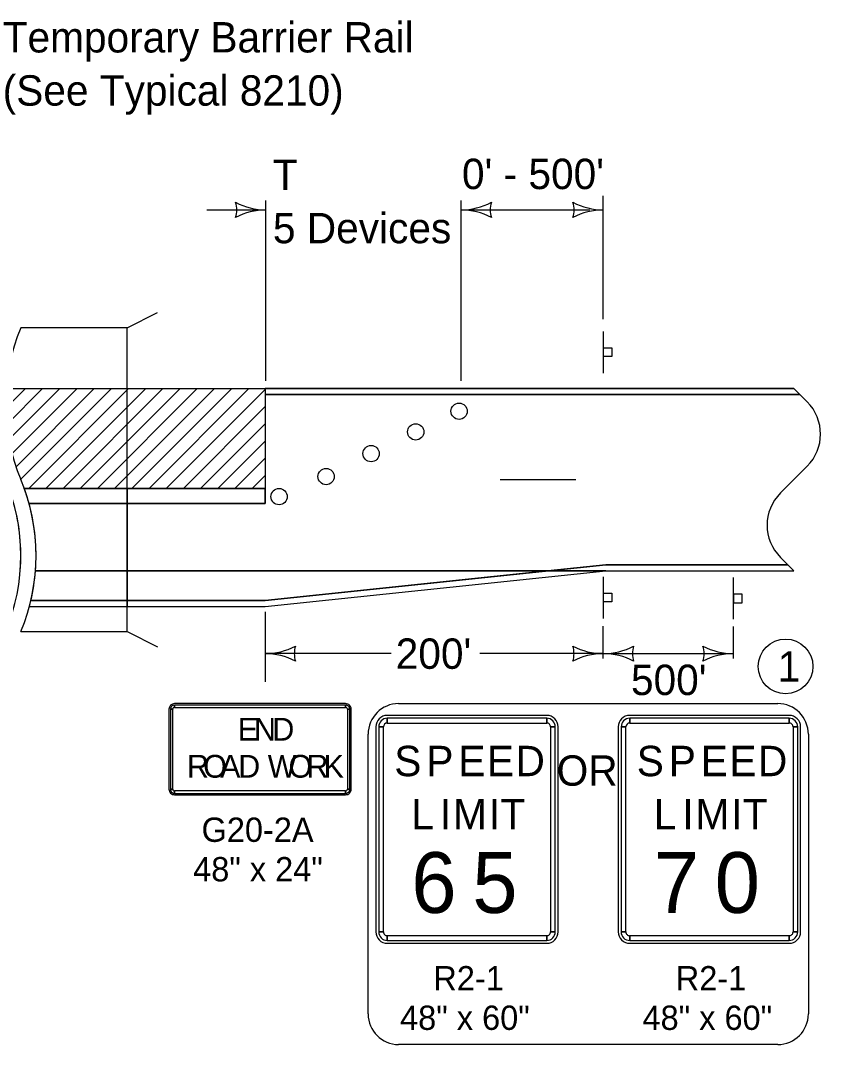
# Model space of a CAD drawing. Extents: x 10133 to 2270741, y 5363 to 1733450.
# Drawn here: x 27091 to 27618, y 6360 to 7034 of the extents above; entities that cross this region are included whole.
import ezdxf

# ---------------------------------------------------------------- set-up
doc = ezdxf.new("R2010")
doc.units = 0
for name, color, linetype in [('dsnNonPlotable', 7, 'Continuous'), ('dsnShtPlotShapeBatchPrint', 7, 'Continuous'), ('dsnStdBorder', 7, 'Continuous'), ('Level 12', 7, 'Continuous'), ('Level 2', 7, 'Continuous')]:
    doc.layers.add(name, color=color, linetype=linetype)

msp = doc.modelspace()

# ---------------------------------------------------------------- linework, layer by layer
at = {"layer": 'dsnNonPlotable'}
for p, q in [((27161.27, 6831.83), (27181.27, 6841.83)), ((27608.87, 6783.04), (27600.09, 6791.83)), ((27591.3, 6723.04), (27608.87, 6740.61)), ((27093.5, 6726.09), (27252.03, 6726.09)), ((27252.03, 6726.09), (27252.03, 6716.09)), ((27252.03, 6716.09), (27096.67, 6716.09)), ((27600.09, 6671.83), (27591.3, 6680.61)), ((27252.03, 6652.32), (27476.23, 6675.83)), ((27100.89, 6671.83), (27476.25, 6671.83)), ((27097.88, 6652.32), (27252.03, 6652.32)), ((27091.27, 6631.83), (27161.27, 6631.83)), ((27161.27, 6631.83), (27181.27, 6621.83))]:
    msp.add_line(p, q, dxfattribs=at)
for points in [[(27161.27, 6631.83), (27161.27, 6831.83), (27091.27, 6831.83)], [(27252.03, 6787.83), (27604.09, 6787.83)], [(27406.7, 6731.83), (27456.7, 6731.83)], [(27406.7, 6731.83), (27456.7, 6731.83)], [(27093.5, 6726.09), (27106.57, 6726.09)], [(27109.74, 6716.09), (27096.67, 6716.09)], [(27476.23, 6675.83), (27596.09, 6675.83)]]:
    msp.add_lwpolyline(points, dxfattribs=at)
for centre, radius, start, end in [((27211.27, 6781.83), 130, 157.38014, 202.61987), ((27587.66, 6761.83), 30, 315, 45), ((26961.27, 6681.83), 130, 337.38014, 22.61987), ((26971.27, 6681.82), 130, 337.38014, 22.61987), ((27612.51, 6701.83), 30, 135, 225)]:
    msp.add_arc(centre, radius, start, end, dxfattribs=at)
at = {"layer": 'dsnShtPlotShapeBatchPrint'}
msp.add_circle((27594.66, 6608.85), 18, dxfattribs=at)
at = {"layer": 'dsnStdBorder'}
for p, q in [((27474.64, 6829.36), (27474.64, 6801.86)), ((27081.31, 6778.85), (27094.29, 6791.83)), ((27081.99, 6768.21), (27105.6, 6791.83)), ((27083.41, 6758.33), (27116.91, 6791.83)), ((27085.47, 6749.07), (27128.23, 6791.83)), ((27088.07, 6740.35), (27139.54, 6791.83)), ((27091.15, 6732.12), (27150.85, 6791.83)), ((27096.43, 6726.09), (27162.17, 6791.83)), ((27107.75, 6726.09), (27173.48, 6791.83)), ((27119.06, 6726.09), (27184.8, 6791.83)), ((27130.38, 6726.09), (27196.11, 6791.83)), ((27141.69, 6726.09), (27207.42, 6791.83)), ((27153, 6726.09), (27218.74, 6791.83)), ((27164.32, 6726.09), (27230.05, 6791.83)), ((27175.63, 6726.09), (27241.36, 6791.83)), ((27186.94, 6726.09), (27252.03, 6791.18)), ((27252.03, 6791.83), (27252.03, 6726.09)), ((27198.26, 6726.09), (27252.03, 6779.87)), ((27209.57, 6726.09), (27252.03, 6768.55)), ((27220.89, 6726.09), (27252.03, 6757.24)), ((27232.2, 6726.09), (27252.03, 6745.93)), ((27243.51, 6726.09), (27252.03, 6734.61)), ((27161.27, 6726.09), (27161.27, 6716.09)), ((27252.03, 6716.09), (27252.03, 6726.09)), ((27161.27, 6716.09), (27252.03, 6716.09)), ((27252.03, 6652.32), (27476.23, 6675.83)), ((27476.23, 6675.83), (27596.09, 6675.83)), ((27474.64, 6667.92), (27474.64, 6640.42)), ((27560.3, 6639.94), (27560.3, 6667.44)), ((27188.75, 6580.63), (27188.75, 6528.13)), ((27189.69, 6580.63), (27191.25, 6580.63)), ((27305, 6584.38), (27192.5, 6584.38)), ((27192.5, 6581.88), (27192.5, 6583.44)), ((27305, 6583.44), (27305, 6581.88)), ((27306.25, 6580.63), (27307.81, 6580.63)), ((27308.75, 6528.13), (27308.75, 6580.63)), ((27437.46, 6576.61), (27332.46, 6576.61)), ((27332.46, 6571.61), (27332.46, 6574.74)), ((27437.46, 6574.74), (27437.46, 6571.61)), ((27597.05, 6576.61), (27492.05, 6576.61)), ((27492.05, 6571.61), (27492.05, 6574.74)), ((27597.05, 6574.74), (27597.05, 6571.61)), ((27324.96, 6569.11), (27324.96, 6434.11)), ((27326.83, 6569.11), (27329.96, 6569.11)), ((27439.96, 6569.11), (27443.08, 6569.11)), ((27444.96, 6434.11), (27444.96, 6569.11)), ((27484.55, 6569.11), (27484.55, 6434.11)), ((27486.43, 6569.11), (27489.55, 6569.11)), ((27599.55, 6569.11), (27602.68, 6569.11)), ((27604.55, 6434.11), (27604.55, 6569.11)), ((27191.25, 6528.13), (27189.69, 6528.13)), ((27192.5, 6525.32), (27192.5, 6526.88)), ((27305, 6526.88), (27305, 6525.32)), ((27307.81, 6528.13), (27306.25, 6528.13)), ((27192.5, 6524.38), (27305, 6524.38)), ((27329.96, 6434.11), (27326.83, 6434.11)), ((27332.46, 6428.49), (27332.46, 6431.61)), ((27437.46, 6431.61), (27437.46, 6428.49)), ((27443.08, 6434.11), (27439.96, 6434.11)), ((27489.55, 6434.11), (27486.43, 6434.11)), ((27492.05, 6428.49), (27492.05, 6431.61)), ((27597.05, 6431.61), (27597.05, 6428.49)), ((27602.68, 6434.11), (27599.55, 6434.11)), ((27332.46, 6426.61), (27437.46, 6426.61)), ((27492.05, 6426.61), (27597.05, 6426.61))]:
    msp.add_line(p, q, dxfattribs=at)
for points in [[(27474.74, 6812.91), (27474.74, 6818.54), (27480.36, 6818.54), (27480.36, 6812.91)], [(27474.74, 6651.47), (27474.74, 6657.09), (27480.36, 6657.09), (27480.36, 6651.47)], [(27560.39, 6656.39), (27560.39, 6650.77), (27566.02, 6650.77), (27566.02, 6656.39)], [(27189.69, 6580.63), (27189.69, 6528.13), (27191.25, 6528.13), (27191.25, 6580.63), (27189.69, 6580.63)], [(27305, 6583.44), (27192.5, 6583.44), (27192.5, 6581.88), (27305, 6581.88), (27305, 6583.44)], [(27307.81, 6528.13), (27307.81, 6580.63), (27306.25, 6580.63), (27306.25, 6528.13), (27307.81, 6528.13)], [(27437.46, 6574.74), (27332.46, 6574.74), (27332.46, 6571.61), (27437.46, 6571.61), (27437.46, 6574.74)], [(27597.05, 6574.74), (27492.05, 6574.74), (27492.05, 6571.61), (27597.05, 6571.61), (27597.05, 6574.74)], [(27326.83, 6569.11), (27326.83, 6434.11), (27329.96, 6434.11), (27329.96, 6569.11), (27326.83, 6569.11)], [(27443.08, 6434.11), (27443.08, 6569.11), (27439.96, 6569.11), (27439.96, 6434.11), (27443.08, 6434.11)], [(27486.43, 6569.11), (27486.43, 6434.11), (27489.55, 6434.11), (27489.55, 6569.11), (27486.43, 6569.11)], [(27602.68, 6434.11), (27602.68, 6569.11), (27599.55, 6569.11), (27599.55, 6434.11), (27602.68, 6434.11)], [(27192.5, 6525.32), (27305, 6525.32), (27305, 6526.88), (27192.5, 6526.88), (27192.5, 6525.32)], [(27332.46, 6428.49), (27437.46, 6428.49), (27437.46, 6431.61), (27332.46, 6431.61), (27332.46, 6428.49)], [(27492.05, 6428.49), (27597.05, 6428.49), (27597.05, 6431.61), (27492.05, 6431.61), (27492.05, 6428.49)]]:
    msp.add_lwpolyline(points, close=True, dxfattribs=at)
for points in [[(27252.03, 6726.09), (27243.51, 6726.09), (27232.2, 6726.09), (27220.89, 6726.09), (27209.57, 6726.09), (27198.26, 6726.09), (27186.94, 6726.09), (27175.63, 6726.09), (27164.32, 6726.09), (27161.27, 6726.09)], [(27339.96, 6584.38), (27589.55, 6584.38)], [(27319.85, 6380.09), (27319.85, 6564.28)], [(27609.66, 6564.28), (27609.66, 6380.09)], [(27589.55, 6359.99), (27339.96, 6359.99)]]:
    msp.add_lwpolyline(points, dxfattribs=at)
for centre in [(27379.76, 6776.86), (27379.76, 6776.86), (27351.17, 6763.25), (27351.17, 6763.25), (27321.84, 6748.94), (27321.84, 6748.94), (27292.22, 6733.84), (27292.22, 6733.84), (27261.26, 6720.62), (27261.26, 6720.62)]:
    msp.add_circle(centre, 5.37, dxfattribs=at)
for centre, radius, start, end in [((27192.5, 6580.63), 3.75, 90.00021, 179.99985), ((27192.5, 6580.63), 2.81, 90.00021, 179.99985), ((27192.5, 6580.63), 1.25, 90.00021, 179.99985), ((27305, 6580.63), 3.75, 0, 90.00021), ((27305, 6580.63), 2.81, 0, 90.00021), ((27305, 6580.63), 1.25, 0, 90.00021), ((27339.96, 6564.28), 20.1, 90, 180), ((27589.55, 6564.28), 20.1, 0, 90), ((27332.46, 6569.11), 7.5, 90.00021, 179.99985), ((27332.46, 6569.11), 5.62, 90.00021, 179.99985), ((27437.46, 6569.11), 7.5, 0, 90.00021), ((27437.46, 6569.11), 5.62, 0, 90.00021), ((27492.05, 6569.11), 7.5, 90.00021, 179.99985), ((27492.05, 6569.11), 5.62, 90.00021, 179.99985), ((27597.05, 6569.11), 7.5, 0, 90.00021), ((27597.05, 6569.11), 5.62, 0, 90.00021), ((27332.46, 6569.11), 2.5, 90.00021, 179.99985), ((27437.46, 6569.11), 2.5, 0, 90.00021), ((27492.05, 6569.11), 2.5, 90.00021, 179.99985), ((27597.05, 6569.11), 2.5, 0, 90.00021), ((27192.5, 6528.13), 3.75, 179.99985, 270.00006), ((27192.5, 6528.13), 2.81, 179.99985, 270.00006), ((27192.5, 6528.13), 1.25, 179.99985, 270.00006), ((27305, 6528.13), 3.75, 270.00006, 0.00027), ((27305, 6528.13), 2.81, 270.00006, 0.00027), ((27305, 6528.13), 1.25, 270.00006, 0.00027), ((27332.46, 6434.11), 7.5, 179.99985, 270.00006), ((27332.46, 6434.11), 5.62, 179.99985, 270.00006), ((27332.46, 6434.11), 2.5, 179.99985, 270.00006), ((27437.46, 6434.11), 7.5, 270.00006, 0.00027), ((27437.46, 6434.11), 5.62, 270.00006, 0.00027), ((27437.46, 6434.11), 2.5, 270.00006, 0.00027), ((27492.05, 6434.11), 7.5, 179.99985, 270.00006), ((27492.05, 6434.11), 5.62, 179.99985, 270.00006), ((27492.05, 6434.11), 2.5, 179.99985, 270.00006), ((27597.05, 6434.11), 7.5, 270.00006, 0.00027), ((27597.05, 6434.11), 5.62, 270.00006, 0.00027), ((27597.05, 6434.11), 2.5, 270.00006, 0.00027), ((27339.96, 6380.09), 20.1, 180, 270), ((27589.55, 6380.09), 20.1, 270, 0)]:
    msp.add_arc(centre, radius, start, end, dxfattribs=at)
at = {"layer": 'Level 12'}
for p, q in [((27474.64, 6837.36), (27474.64, 6918.57)), ((27213.78, 6909.35), (27252.62, 6909.35)), ((27252.57, 6796.87), (27252.57, 6915.58)), ((27381.06, 6796.87), (27381.06, 6915.58)), ((27381.06, 6909.35), (27465.78, 6909.35)), ((27252.03, 6644.9), (27252.03, 6598.66)), ((27474.64, 6614.08), (27474.64, 6635.32)), ((27560.3, 6614.08), (27560.3, 6635.05)), ((27334.99, 6617.28), (27252.03, 6617.28)), ((27474.64, 6617.28), (27393.32, 6617.28)), ((27474.64, 6617.28), (27560.3, 6617.28))]:
    msp.add_line(p, q, dxfattribs=at)
for centre, radius, start, end in [((27216.99, 6909.35), 16.42, 342.26665, 17.73335), ((27252.62, 6951.85), 42.5, 241.92751, 270), ((27252.62, 6866.85), 42.5, 90, 118.07249), ((27381, 6951.85), 42.5, 270, 298.07249), ((27381, 6866.85), 42.5, 61.92751, 90), ((27416.63, 6909.35), 16.42, 162.26665, 197.73335), ((27439.08, 6909.35), 16.42, 342.26665, 17.73335), ((27474.71, 6951.85), 42.5, 241.92751, 270), ((27474.71, 6866.85), 42.5, 90, 118.07249), ((27252.03, 6659.78), 42.5, 270, 298.07249), ((27287.67, 6617.28), 16.42, 162.26665, 197.73335), ((27439.01, 6617.28), 16.42, 342.26665, 17.73335), ((27474.64, 6659.78), 42.5, 241.92751, 270), ((27474.64, 6659.78), 42.5, 270, 298.07249), ((27510.28, 6617.28), 16.42, 162.26665, 197.73335), ((27524.66, 6617.28), 16.42, 342.26665, 17.73335), ((27560.3, 6659.78), 42.5, 241.92751, 270), ((27252.03, 6574.78), 42.5, 61.92751, 90), ((27474.64, 6574.78), 42.5, 90, 118.07249), ((27474.64, 6574.78), 42.5, 61.92751, 90), ((27560.3, 6574.78), 42.5, 90, 118.07249)]:
    msp.add_arc(centre, radius, start, end, dxfattribs=at)
at = {"layer": 'Level 2'}
for p, q in [((27081.66, 6791.83), (27600.09, 6791.83)), ((27600.09, 6791.83), (27252.03, 6791.83)), ((27252.03, 6791.83), (27252.03, 6787.83)), ((27252.03, 6787.83), (27604.09, 6787.83)), ((27604.09, 6787.83), (27252.03, 6787.83)), ((27252.03, 6787.83), (27252.03, 6779.87)), ((27604.09, 6787.83), (27600.09, 6791.83)), ((27608.87, 6783.04), (27604.09, 6787.83)), ((27252.03, 6779.87), (27252.03, 6768.55)), ((27252.03, 6768.55), (27252.03, 6757.24)), ((27591.3, 6723.04), (27608.87, 6740.61)), ((27161.27, 6716.09), (27161.27, 6726.09)), ((27252.03, 6726.09), (27252.03, 6716.09)), ((27096.67, 6716.09), (27109.74, 6716.09)), ((27109.74, 6716.09), (27161.27, 6716.09)), ((27161.27, 6671.83), (27161.27, 6716.09)), ((27252.03, 6716.09), (27161.27, 6716.09)), ((27161.27, 6716.09), (27161.27, 6671.83)), ((27596.09, 6675.83), (27591.3, 6680.61)), ((27476.23, 6675.83), (27438.08, 6671.83)), ((27438.09, 6671.83), (27476.23, 6675.83)), ((27596.09, 6675.83), (27476.23, 6675.83)), ((27476.23, 6675.83), (27596.09, 6675.83)), ((27600.09, 6671.83), (27596.09, 6675.83)), ((27161.27, 6671.83), (27100.89, 6671.83)), ((27100.89, 6671.83), (27161.27, 6671.83)), ((27394.43, 6671.83), (27161.27, 6671.83)), ((27161.27, 6671.83), (27161.27, 6652.32)), ((27161.27, 6652.32), (27161.27, 6671.83)), ((27161.27, 6671.83), (27438.09, 6671.83)), ((27252.03, 6648.32), (27476.23, 6671.83)), ((27252.03, 6652.32), (27438.08, 6671.83)), ((27252.03, 6648.32), (27476.23, 6671.83)), ((27438.08, 6671.83), (27252.03, 6652.32)), ((27394.43, 6671.83), (27600.09, 6671.83)), ((27438.08, 6671.83), (27394.43, 6671.83)), ((27476.23, 6671.83), (27438.08, 6671.83)), ((27438.08, 6671.83), (27600.09, 6671.83)), ((27096.88, 6648.32), (27161.27, 6648.32)), ((27096.88, 6648.32), (27252.03, 6648.32)), ((27096.88, 6648.32), (27109.94, 6648.32)), ((27097.88, 6652.32), (27110.94, 6652.32)), ((27110.94, 6652.32), (27097.88, 6652.32)), ((27110.94, 6652.32), (27161.27, 6652.32)), ((27161.27, 6652.32), (27110.94, 6652.32)), ((27161.27, 6652.32), (27252.03, 6652.32)), ((27252.03, 6652.32), (27161.27, 6652.32)), ((27161.27, 6652.32), (27161.27, 6648.32)), ((27161.27, 6648.32), (27161.27, 6652.32)), ((27161.27, 6648.32), (27252.03, 6648.32))]:
    msp.add_line(p, q, dxfattribs=at)
for points in [[(27604.09, 6787.83), (27604.09, 6787.83)], [(27604.09, 6787.83), (27604.09, 6787.83)], [(27252.03, 6757.24), (27252.03, 6745.93), (27252.03, 6734.61), (27252.03, 6726.09)], [(27161.27, 6726.09), (27153, 6726.09), (27141.69, 6726.09), (27130.38, 6726.09), (27119.06, 6726.09), (27107.75, 6726.09), (27106.57, 6726.09), (27096.43, 6726.09), (27093.5, 6726.09)], [(27161.27, 6716.09), (27109.74, 6716.09), (27096.67, 6716.09)], [(27596.09, 6675.83), (27596.09, 6675.83)], [(27596.09, 6675.83), (27596.09, 6675.83)], [(27394.43, 6671.83), (27394.43, 6671.83)]]:
    msp.add_lwpolyline(points, dxfattribs=at)
for centre, radius, start, end in [((27587.66, 6761.83), 30, 315, 45), ((26971.27, 6681.82), 130, 15.28322, 19.90817), ((27612.51, 6701.83), 30, 135, 225), ((26961.27, 6681.83), 130, 355.58827, 15.28231), ((26971.27, 6681.82), 130, 355.58916, 15.28322), ((26971.27, 6681.82), 130, 346.88255, 355.58916), ((26971.27, 6681.82), 130, 345.06535, 346.88255)]:
    msp.add_arc(centre, radius, start, end, dxfattribs=at)

# ---------------------------------------------------------------- texts
at = {"layer": 'dsnShtPlotShapeBatchPrint'}
msp.add_text('1', height=20, dxfattribs=at).set_placement((27589.46, 6598.85))
at = {"layer": 'dsnStdBorder'}
for s, height, p in [('E', 15, (27234.08, 6560.01)), ('N', 15, (27244.7, 6560.01)), ('D', 15, (27256.78, 6560.01)), ('S', 20, (27337.08, 6536.61)), ('P', 20, (27358.18, 6536.61)), ('E', 20, (27379.27, 6536.61)), ('E', 20, (27398.08, 6536.61)), ('D', 20, (27416.89, 6536.61)), ('S', 20, (27496.68, 6536.61)), ('P', 20, (27517.77, 6536.61)), ('E', 20, (27538.86, 6536.61)), ('E', 20, (27557.67, 6536.61)), ('D', 20, (27576.48, 6536.61)), ('R', 15, (27200.61, 6535.63)), ('O', 15, (27211.3, 6535.63)), ('A', 15, (27222.45, 6535.63)), ('D', 15, (27234.31, 6535.63)), ('W', 15, (27253.76, 6535.63)), ('O', 15, (27267.5, 6535.63)), ('R', 15, (27279.26, 6535.63)), ('K', 15, (27290.56, 6535.63)), ('OR', 20, (27443.98, 6530.33)), ('L', 20, (27348.33, 6501.61)), ('I', 20, (27367.14, 6501.61)), ('M', 20, (27375.74, 6501.61)), ('I', 20, (27399.33, 6501.61)), ('T', 20, (27406.89, 6501.61)), ('L', 20, (27507.93, 6501.61)), ('I', 20, (27526.74, 6501.61)), ('M', 20, (27535.33, 6501.61)), ('I', 20, (27558.92, 6501.61)), ('T', 20, (27566.48, 6501.61)), ('G20-2A', 16, (27210.22, 6493.38)), ('6', 40, (27348.33, 6446.61)), ('5', 40, (27388.45, 6446.61)), ('7', 40, (27507.93, 6446.61)), ('0', 40, (27548.05, 6446.61)), ('48" x 24"', 16, (27204.68, 6467.38)), ('R2-1', 16, (27362.79, 6395.61)), ('R2-1', 16, (27522.39, 6395.61)), ('48" x 60"', 16, (27340.89, 6369.61)), ('48" x 60"', 16, (27500.48, 6369.61))]:
    msp.add_text(s, height=height, dxfattribs=at).set_placement(p)
at = {"layer": 'Level 12'}
for s, p in [('Temporary Barrier Rail', (27079.31, 7012.98)), ('(See Typical 8210)', (27079.31, 6977.98)), ("0' - 500'", (27381.63, 6923.06)), ('T', (27257.19, 6922.4)), ('5 Devices', (27257.19, 6887.4)), ("200'", (27338.03, 6607.28)), ("500'", (27492.89, 6590.02))]:
    msp.add_text(s, height=20, dxfattribs=at).set_placement(p)

doc.saveas('drawing.dxf')
